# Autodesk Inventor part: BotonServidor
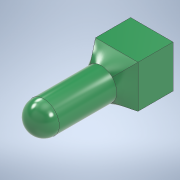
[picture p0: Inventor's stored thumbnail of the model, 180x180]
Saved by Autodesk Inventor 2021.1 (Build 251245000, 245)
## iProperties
Created: 2021-06
Part Number: BotonServidor
Material: Genérico
Document SubType Name: Modeling
Designer: Ricardo
Density: 1 g/cm^3
Appearance: Valor por defecto
Author: Ricardo
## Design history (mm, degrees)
sketch "Boceto1"
  geometry: L1 (-1.5, -1.5)-(1.5, -1.5); L2 (1.5, -1.5)-(1.5, 1.5); L3 (1.5, 1.5)-(-1.5, 1.5); L4 (-1.5, 1.5)-(-1.5, -1.5); L5 (-1.5, -1.5)-(1.5, 1.5); L6 (1.5, -1.5)-(-1.5, 1.5); L7 (-4.25, -4.25)-(4.25, -4.25); L8 (4.25, -4.25)-(4.25, 4.25); L9 (4.25, 4.25)-(-4.25, 4.25); L10 (-4.25, 4.25)-(-4.25, -4.25); L11 (-4.25, -4.25)-(4.25, 4.25); L12 (4.25, -4.25)-(-4.25, 4.25); L13 (-5.45, 5.45)-(5.45, 5.45); L14 (5.45, 5.45)-(5.45, -5.45); L15 (5.45, -5.45)-(-5.45, -5.45); L16 (-5.45, -5.45)-(-5.45, 5.45); 1 further point
  constraints: 32 end point, 6 parallel, 4 midpoint, 3 perpendicular, 2 horizontal, 3 other
  dimensions: "d0" = 3 distance of L3.end L2.end; "d1" = 3 distance of L2.end L1.end; "d2" = 8.5 distance of L9.end L8.end; "d3" = 8.5 distance of L8.end L7.end; "d4" = 1.2 distance between parallel lines of L9 L13
extrude "Extrusión1" new body sketch "Boceto1" distance "d5" = 5; taper "d6" = 0 deg
extrude "Extrusión2" join sketch "Boceto1" distance "d7" = 4; taper "d8" = 0 deg
node "Superficie envolvente"
node "Plano de trabajo2"
sketch "Boceto2"
  geometry: L1 (-1.5, -1.5)-(1.5, -1.5) reference; L2 (-1.5, 1.5)-(-1.5, -1.5) reference; L3 (1.5, 1.5)-(-1.5, 1.5) reference; L4 (1.5, -1.5)-(1.5, 1.5) reference; C1 r 4 at (0, 0); 1 further point
  constraints: 1 centre point, 1 coincident
  dimensions: "d11" = 8 diameter of C1
feature "Solevación1" dims "d12" = 0, "d13" = 90 deg, "d14" = 0, "d15" = 90 deg
  node "Aristas1"
node "Plano de trabajo3"
extrude "Extrusión3" join sketch "Boceto2" stored distance "d17" = 4; taper "d18" = 0 deg
sketch "Boceto3"
  geometry: C1 r 4 at (0, 0); 1 further point
  constraints: 1 centre point, 1 coincident
  dimensions: "d19" = 8 diameter of C1
extrude "Extrusión4" join sketch "Boceto3" distance "d20" = 3; taper "d21" = 0 deg
sketch "Boceto4"
  geometry: L1 (0, 4)-(0, -4); A1 r 4 centre (0, 0) between (0, 4) and (0, -4) reference; 1 further point
  constraints: 2 end point, 2 point on circle, 1 vertical
revolve "Revolución1" sketch "Boceto4" stored, may be unused: angle "d22" = 90 deg
node "Sólido1"
node "Contorno proyectado1"
other parameters: "d9" = -15.75, "d10" = -8, "d16" = -4
